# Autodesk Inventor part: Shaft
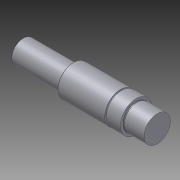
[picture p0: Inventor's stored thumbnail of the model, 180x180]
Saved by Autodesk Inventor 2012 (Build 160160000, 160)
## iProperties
Created: 2011-12
Part Number: Shaft
Material: Steel
Document SubType Name: Modeling
Designer: Admin
Density: 1 g/cm^3
CustomPartVersion: 1
Author: Admin
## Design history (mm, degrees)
sketch "Main Sketch"
  geometry: L1 (0, 0)-(131.5, 0) reference; L2 (0, 0)-(0, 11); L3 (53, 17.5)-(53, 15); L4 (0, 11)-(48, 11); L5 (101.5, 15)-(101.5, 12.5); L6 (53, 15)-(101.5, 15); L7 (131.5, 12.5)-(131.5, 0); L8 (101.5, 12.5)-(131.5, 12.5); L9 (48, 11)-(48, 17.5); L10 (48, 17.5)-(53, 17.5)
  constraints: 20 end point, 5 vertical, 2 horizontal
  dimensions: "d3" = 22 diameter of L4 L1 (derived); "d9" = 30 diameter of L6 L1 (derived); "d18" = 25 diameter of L8 L1 (derived); "d19" = 35 diameter of L10 L1 (derived)
revolve "Revolution1" sketch "Main Sketch" stored, may be unused: angle "d4" = 0 deg
chamfer "Chamfer8" distance "d35" = 0.5; stored, may be unused: second distance "d36" = 0.125, angle "d37" = 45 deg
node "Relief2"
fillet "Fillet5" dims "d30" = 2
chamfer "Chamfer7" distance "d31" = 0.5; stored, may be unused: second distance "d32" = 0.125, angle "d33" = 45 deg
chamfer "Chamfer5" distance "d23" = 0.5; stored, may be unused: second distance "d24" = 0.125, angle "d25" = 45 deg
node "Relief1"
node "Retaining Ring Groove1"
body "Solid1"
feature "iFeature27:1"
feature "iFeature2:1"
feature "iFeature2:2"
other parameters: "d0" = 0, "d1" = 0, "d2" = 0
